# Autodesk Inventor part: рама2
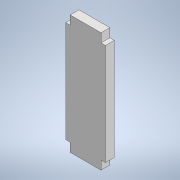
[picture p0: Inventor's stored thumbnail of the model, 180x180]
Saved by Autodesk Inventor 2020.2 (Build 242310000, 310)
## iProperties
Created: 2020-04
Part Number: рама2
Material: Типовые
Document SubType Name: Modeling
Designer: Алексей
Density: 1 g/cm^3
Appearance: По умолчанию
Author: Алексей
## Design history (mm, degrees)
sketch "Эскиз1"
  geometry: L1 (-14, 54)-(0, 54) reference; L2 (0, 50)-(-14, 50) reference; L3 (-14, 4)-(0, 4) reference; L4 (0, 0)-(-14, 0) reference; L5 (2, 4)-(-16, 4); L6 (-16, 4)-(-16, 50); L7 (-16, 50)-(2, 50); L8 (2, 50)-(2, 4); L9 (-14, 50)-(-14, 54) reference; L10 (0, 50)-(0, 54) reference; L11 (-14, 0)-(-14, 4) reference; L12 (0, 0)-(0, 4) reference; 7 further points
  constraints: 8 end point, 2 collinear, 2 parallel, 1 horizontal, 1 perpendicular
extrude "Выдавливание1" new body sketch "Эскиз1" distance "d2" = 4; taper "d3" = 0 deg
node "Твердое тело1"
node "Ссылка1"
node "Ссылка2"
